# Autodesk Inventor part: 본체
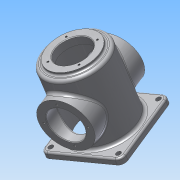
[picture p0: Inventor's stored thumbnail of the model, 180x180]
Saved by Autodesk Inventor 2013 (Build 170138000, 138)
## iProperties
Created: 2015-10
Part Number: 본체
Material: 알루미늄 6061
Document SubType Name: Modeling
Designer: Administrator
Density: 2.71 g/cm^3
Mass: 985.996 g
Surface Area: 1037.37 cm^2
Volume: 363.836 cm^3
Author: Administrator
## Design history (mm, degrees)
sketch "스케치1"
  geometry: L1 (60, -60)-(-60, -60); L2 (-60, -60)-(-60, 60); L3 (-60, 60)-(60, 60); L4 (60, 60)-(60, -60); L5 (60, -60)-(-60, 60); L6 (-60, -60)-(60, 60); 1 further point
  constraints: 12 end point, 2 midpoint, 2 parallel, 1 horizontal, 1 perpendicular
  dimensions: "d0" = 120 distance of L2.end L3.end; "d1" = 120 distance of L1.end L2.end
extrude "돌출1" new body sketch "스케치1" distance "d2" = 10; taper "d3" = 0 deg
sketch "스케치2"
  geometry: C1 r 50 at (0, 0); 1 further point
  constraints: 1 centre point, 1 coincident
  dimensions: "d4" = 100 diameter of C1
extrude "돌출2" join sketch "스케치2" distance "d5" = 110; taper "d6" = 0 deg
sketch "스케치3"
  geometry: C1 r 45 at (0, 0); 1 further point
  constraints: 1 centre point, 1 coincident
  dimensions: "d7" = 90 diameter of C1
extrude "돌출3" cut sketch "스케치3" distance "d8" = 112; taper "d9" = 0 deg
sketch "스케치4"
  geometry: C1 r 50 at (0, 0) reference; C2 r 40 at (0, 0)
  constraints: 1 centre point, 1 coincident
  dimensions: "d10" = 80 diameter of C2
extrude "돌출4" join sketch "스케치4" distance "d11" = 5; taper "d12" = 0 deg
node "작업 평면1"
sketch "스케치5"
  geometry: L1 (60, 0)-(-60, 0) reference; C1 r 40 at (0, 60); 1 further point
  constraints: 1 centre point, 1 vertical alignment
  dimensions: "d14" = 80 diameter of C1; "d15" = 60 distance from line of L1 C1.centre
extrude "돌출5" join sketch "스케치5" stored distance "d16" = 5; taper "d17" = 0 deg
sketch "스케치6"
  geometry: C1 r 40 at (0, 0) reference; 2 further points
  constraints: 1 vertical alignment
  dimensions: "d18" = 32.5 distance of C1.centre point (0, 32.5)
hole "구멍1" sketch "스케치6" at (0, 32.5) diameter "d19" = 3.242; stored, may be unused: countersink angle "d23" = 90 deg, drill point angle "d25" = 118 deg; dims "d20" = 8, "d21" = 4, "d22" = 2, "d24" = 10
hole "구멍2" diameter "d31" = 54; stored, may be unused: countersink angle "d35" = 90 deg, drill point angle "d37" = 0 deg; dims "d29" = 10, "d30" = 10, "d32" = 8, "d33" = 4, "d34" = 2, "d36" = 10
hole "구멍3" diameter "d40" = 54; stored, may be unused: countersink angle "d44" = 90 deg, drill point angle "d46" = 0 deg; dims "d38" = 10, "d39" = 10, "d41" = 8, "d42" = 4, "d43" = 2, "d45" = 10
sketch "스케치7"
  geometry: L1 (0, 0)-(0, 40); L2 (0, 0)-(22.981, 22.981); 1 further point
  constraints: 4 end point, 1 coincident, 1 vertical, 1 vertical alignment, 1 other
  dimensions: "d47" = 45 deg angle of L2 L1; "d48" = 32.5 distance of L1.start L2.end
hole "구멍4" sketch "스케치7" at (22.981, 22.981) diameter "d49" = 3.242; stored, may be unused: countersink angle "d53" = 90 deg, drill point angle "d55" = 118 deg; dims "d50" = 8, "d51" = 4, "d52" = 2, "d54" = 10
fillet "모깎기1" dims "d59" = 10
sketch "스케치8"
  geometry: A1 r 10 centre (-50, -50) between (-60, -50) and (-50, -60) reference; A2 r 10 centre (50, -50) between (50, -60) and (60, -50) reference; A3 r 10 centre (50, 50) between (60, 50) and (50, 60) reference; A4 r 10 centre (-50, 50) between (-50, 60) and (-60, 50) reference; 4 further points
  constraints: 4 coincident
hole "구멍5" sketch "스케치8" at (-50, 50), (50, 50), (50, -50), (-50, -50) diameter "d60" = 8; stored, may be unused: countersink angle "d64" = 90 deg, drill point angle "d66" = 0 deg; dims "d61" = 8, "d62" = 4, "d63" = 2, "d65" = 10
node "작업 평면2"
sketch "스케치9"
  geometry: 2 further points
  constraints: 1 horizontal alignment, 1 other
  dimensions: "d68" = 70 distance of point (0, 0) point (-70, 0)
feature "엠보싱1" sketch "스케치9" dims "d0" = 120, "d1" = 120, "d69" = 0.5, "d70" = 0
chamfer "모따기1" distance "d71" = 3; stored, may be unused: second distance "d72" = 2, angle "d73" = 45 deg
chamfer "모따기2" distance "d74" = 1; stored, may be unused: second distance "d75" = 2, angle "d76" = 45 deg
fillet "모깎기2" dims "d77" = 3
fillet "모깎기3" dims "d78" = 5
fillet "모깎기4" dims "d79" = 3
node "솔리드1"
pattern_circular "원형 패턴1" dims angle "d27" = 360 deg
mirror "대칭1"
pattern_circular "원형 패턴2" dims angle "d57" = 360 deg
other parameters: "d13" = 62
